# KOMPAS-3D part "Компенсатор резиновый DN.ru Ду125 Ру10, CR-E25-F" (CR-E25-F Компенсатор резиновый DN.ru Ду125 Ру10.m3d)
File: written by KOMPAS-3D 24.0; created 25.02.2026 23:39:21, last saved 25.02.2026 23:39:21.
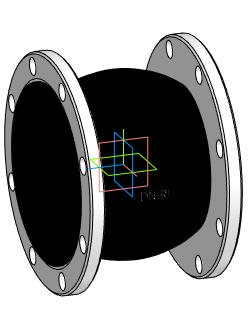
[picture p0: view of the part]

Document properties: Автор: DN.RU; Полное имя файла: D:\PROJECT CAD\DN.RU\...178(4)(ACTUALE). CR-E25-F Компенсатор резиновый DN.ru Ру10-16\DN125_PN10\CR-E25-F Компенсатор резиновый DN.ru Ду125 Ру10.m3d

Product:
- Body: Твердое тело2  | qty 1
    Масса: 19.466313
- Part/product: Компенсатор резиновый DN.ru Ду125 Ру10  | designation CR-E25-F
    Масса: 10.71
    Раздел спецификации: Прочие изделия
    Комментарий: D140-02166
    Примечание: D140-02166
    additional columns: Типовые

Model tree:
1. Твердое тело2  (labels: Твердое тело2)

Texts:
  CR-E25-F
